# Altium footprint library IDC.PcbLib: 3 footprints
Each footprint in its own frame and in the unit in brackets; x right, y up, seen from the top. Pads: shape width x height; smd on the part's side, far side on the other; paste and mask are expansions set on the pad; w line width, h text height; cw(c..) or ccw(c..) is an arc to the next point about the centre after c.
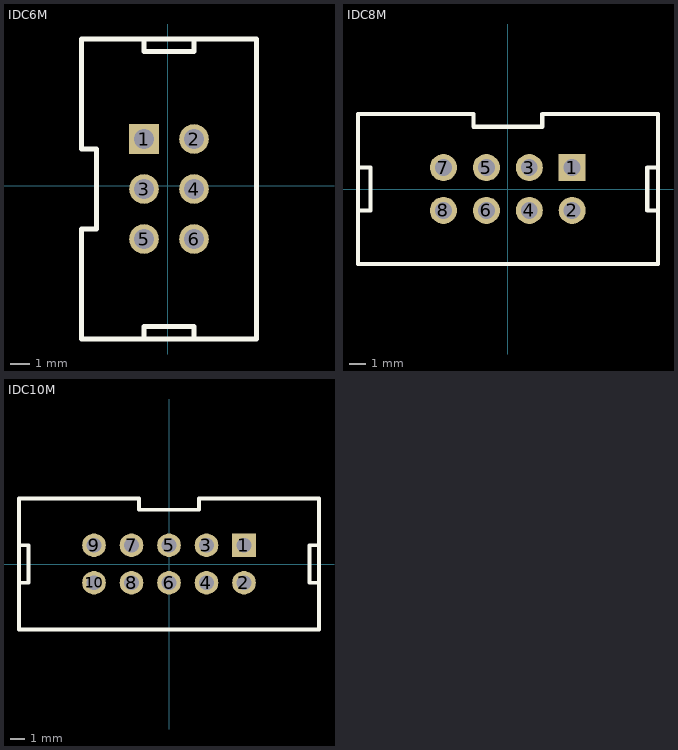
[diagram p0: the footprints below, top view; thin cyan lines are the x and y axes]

## IDC6M [mm]
pads (6):
  rect 1.5x1.5 hole 1: 1(-1.2,2.37)
  round 1.5 hole 1: 2(1.34,2.37) 3(-1.2,-0.17) 4(1.34,-0.17) 5(-1.2,-2.71) 6(1.34,-2.71)
Top Overlay:
  lines w0.254: -1.2,-7.79 -1.2,-7.155 1.34,-7.155 1.34,-7.79 ; -1.2,7.45 -1.2,6.815 1.34,6.815 1.34,7.45 ; -4.375,-7.79 -4.375,-2.202 -3.613,-2.202 -3.613,1.862 -4.375,1.862 -4.375,7.45 4.515,7.45 4.515,-7.79 -4.375,-7.79

## IDC8M [mm]
pads (8):
  rect 1.6x1.6 hole 1: 1(3.81,1.27)
  round 1.6 hole 1: 2(3.81,-1.27) 3(1.27,1.27) 4(1.27,-1.27) 5(-1.27,1.27) 6(-1.27,-1.27) 7(-3.81,1.27) 8(-3.81,-1.27)
Top Overlay:
  lines w0.254: -8.763,-1.27 -8.128,-1.27 -8.128,1.27 -8.763,1.27 ; 8.89,-1.27 8.255,-1.27 8.255,1.27 8.89,1.27 ; -8.87,-4.445 -8.87,4.445 -2.032,4.445 -2.032,3.683 2.032,3.683 2.032,4.445 8.89,4.445 8.89,-4.445 -8.87,-4.445

## IDC10M [mm]
pads (10):
  rect 1.6x1.6 hole 1: 1(5.08,1.27)
  round 1.6 hole 1: 2(5.08,-1.27) 3(2.54,1.27) 4(2.54,-1.27) 5(0,1.27) 6(0,-1.27) 7(-2.54,1.27) 8(-2.54,-1.27) 9(-5.08,1.27) 10(-5.08,-1.27)
Top Overlay:
  lines w0.254: -10.16,-1.27 -9.525,-1.27 -9.525,1.27 -10.16,1.27 ; 10.16,-1.27 9.525,-1.27 9.525,1.27 10.16,1.27 ; -10.16,-4.445 10.16,-4.445 10.16,4.445 2.032,4.445 2.032,3.683 -2.032,3.683 -2.032,4.445 -10.16,4.445 -10.16,-4.445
